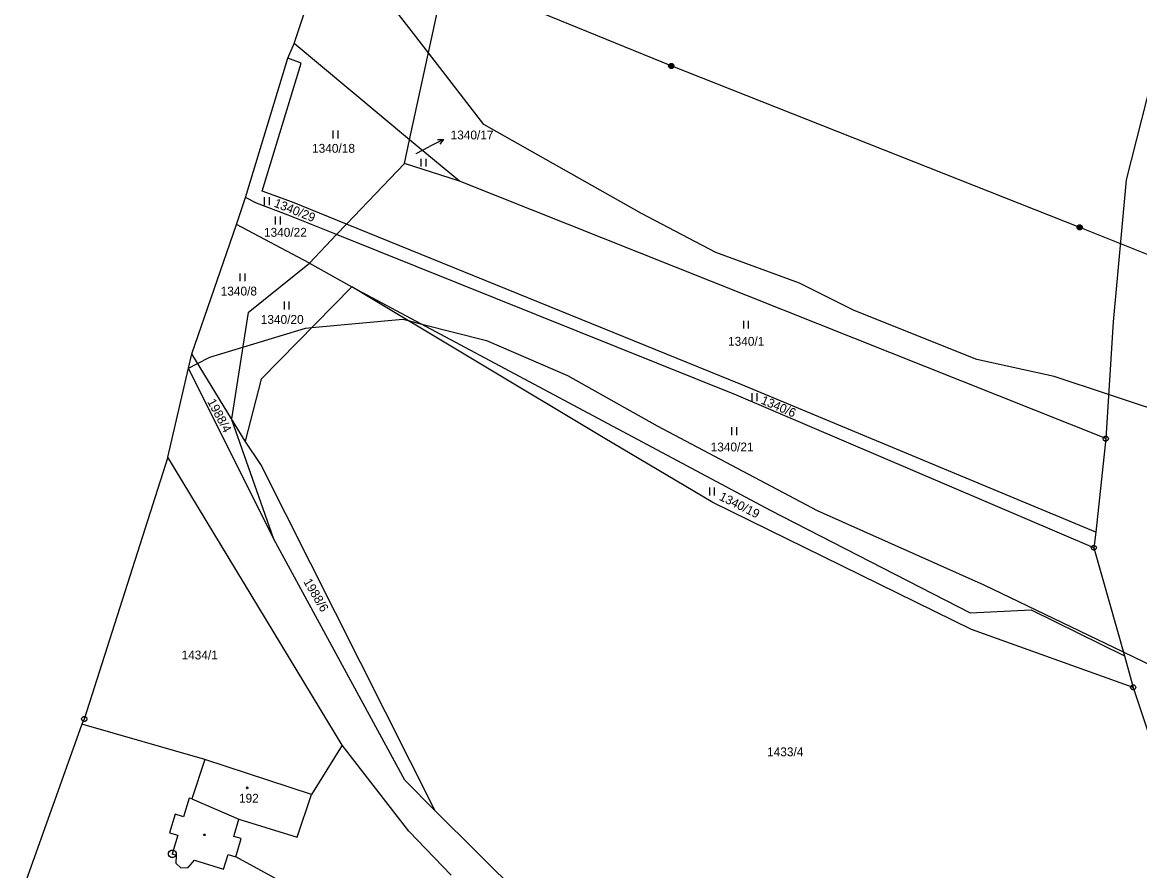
# Model space of a CAD drawing. Extents: x -789470 to -786707, y -1118640 to -1114455.
# Drawn here: x -787522.2 to -787308.1, y -1117682.3 to -1117519.8 of the extents above; entities that cross this region are included whole.
import ezdxf

# ---------------------------------------------------------------- set-up
doc = ezdxf.new("R2010")
doc.units = 0
for name, color, linetype in [('1', 7, 'Continuous'), ('11', 7, 'Continuous'), ('12', 7, 'Continuous'), ('2', 7, 'Continuous'), ('3', 7, 'Continuous'), ('4', 7, 'Continuous'), ('5', 7, 'Continuous'), ('6', 7, 'Continuous'), ('7', 7, 'Continuous'), ('8', 7, 'Continuous')]:
    doc.layers.add(name, color=color, linetype=linetype)

msp = doc.modelspace()

# ---------------------------------------------------------------- linework, layer by layer
at = {"layer": '1'}
for p, q in [((-787470.14, -1117523.83), (-787454.54, -1117476.95)), ((-787448.02, -1117542.27), (-787438.18, -1117497.19)), ((-787471.33, -1117526.59), (-787470.14, -1117523.83)), ((-787448.02, -1117542.27), (-787470.14, -1117523.83)), ((-787303.89, -1117523.03), (-787310.72, -1117549.93)), ((-787479.42, -1117553.33), (-787471.33, -1117526.59)), ((-787468.81, -1117527.55), (-787471.33, -1117526.59)), ((-787476.28, -1117552.12), (-787468.81, -1117527.55)), ((-787449, -1117546.78), (-787448.02, -1117542.27)), ((-787438.47, -1117550.22), (-787448.02, -1117542.27)), ((-787460.09, -1117558.43), (-787449, -1117546.78)), ((-787438.47, -1117550.22), (-787449, -1117546.78)), ((-787314.62, -1117599.54), (-787438.47, -1117550.22)), ((-787310.72, -1117549.93), (-787313.18, -1117577.14)), ((-787470.43, -1117554.23), (-787476.28, -1117552.12)), ((-787481.2, -1117558.5), (-787479.42, -1117553.33)), ((-787477.32, -1117554.4), (-787479.42, -1117553.33)), ((-787471.27, -1117556.71), (-787477.32, -1117554.4)), ((-787460.09, -1117558.43), (-787470.43, -1117554.23)), ((-787462, -1117560.43), (-787471.27, -1117556.71)), ((-787489.74, -1117583.27), (-787481.2, -1117558.5)), ((-787467.2, -1117565.89), (-787481.2, -1117558.5)), ((-787462, -1117560.43), (-787460.09, -1117558.43)), ((-787384.46, -1117589.14), (-787460.09, -1117558.43)), ((-787467.2, -1117565.89), (-787462, -1117560.43)), ((-787385.34, -1117591.22), (-787462, -1117560.43)), ((-787478.95, -1117575.34), (-787467.2, -1117565.89)), ((-787467.2, -1117565.89), (-787459.04, -1117570.42)), ((-787459.04, -1117570.42), (-787476.45, -1117588.13)), ((-787459.04, -1117570.42), (-787378.91, -1117613.22)), ((-787410.93, -1117599.34), (-787459.04, -1117570.42)), ((-787478.95, -1117575.34), (-787482.1, -1117595.77)), ((-787313.18, -1117577.14), (-787314.62, -1117599.54)), ((-787490.38, -1117586.02), (-787489.74, -1117583.27)), ((-787482.1, -1117595.77), (-787489.74, -1117583.27)), ((-787494.34, -1117603.08), (-787490.38, -1117586.02)), ((-787474.03, -1117618.82), (-787490.38, -1117586.02)), ((-787476.45, -1117588.13), (-787479.51, -1117600.01)), ((-787316.9, -1117620.47), (-787385.34, -1117591.22)), ((-787316.54, -1117617.47), (-787384.46, -1117589.14)), ((-787474.03, -1117618.82), (-787482.1, -1117595.77)), ((-787479.51, -1117600.01), (-787482.1, -1117595.77)), ((-787389.9, -1117611.79), (-787410.93, -1117599.34)), ((-787314.62, -1117599.54), (-787316.54, -1117617.47)), ((-787476.53, -1117604.49), (-787479.51, -1117600.01)), ((-787494.34, -1117603.08), (-787510.33, -1117653.28)), ((-787460.9, -1117658.31), (-787494.34, -1117603.08)), ((-787443.11, -1117670.88), (-787476.53, -1117604.49)), ((-787340.35, -1117636.15), (-787389.9, -1117611.79)), ((-787378.91, -1117613.22), (-787340.58, -1117632.95)), ((-787448.94, -1117665.02), (-787474.03, -1117618.82)), ((-787316.54, -1117617.47), (-787316.9, -1117620.47)), ((-787316.9, -1117620.47), (-787311.06, -1117641.19)), ((-787340.58, -1117632.95), (-787328.89, -1117632.33)), ((-787328.89, -1117632.33), (-787311.06, -1117641.19)), ((-787309.36, -1117647.22), (-787340.35, -1117636.15)), ((-787311.06, -1117641.19), (-787309.36, -1117647.22)), ((-787309.36, -1117647.22), (-787300.47, -1117674.13)), ((-787510.33, -1117653.28), (-787510.81, -1117654.24)), ((-787510.81, -1117654.24), (-787522.2, -1117686.13)), ((-787487.21, -1117661.01), (-787510.81, -1117654.24)), ((-787460.9, -1117658.31), (-787466.81, -1117667.72)), ((-787448.15, -1117674.77), (-787460.9, -1117658.31)), ((-787487.21, -1117661.01), (-787489.7, -1117668.58)), ((-787466.81, -1117667.72), (-787487.21, -1117661.01)), ((-787443.11, -1117670.88), (-787448.94, -1117665.02)), ((-787469.52, -1117675.95), (-787466.81, -1117667.72)), ((-787490.22, -1117668.42), (-787491.32, -1117672.03)), ((-787489.7, -1117668.58), (-787490.22, -1117668.42)), ((-787492.94, -1117671.54), (-787494.01, -1117675.06)), ((-787491.32, -1117672.03), (-787492.94, -1117671.54)), ((-787481.71, -1117675.77), (-787480.7, -1117672.45)), ((-787480.7, -1117672.45), (-787469.52, -1117675.95)), ((-787425.55, -1117688.26), (-787443.11, -1117670.88)), ((-787494.01, -1117675.06), (-787492.4, -1117675.55)), ((-787492.4, -1117675.55), (-787493.48, -1117679.11)), ((-787480.29, -1117676.2), (-787481.71, -1117675.77)), ((-787481.31, -1117679.68), (-787480.29, -1117676.2)), ((-787440.01, -1117683.2), (-787448.15, -1117674.77)), ((-787493.48, -1117679.11), (-787492.7, -1117679.35)), ((-787492.7, -1117679.35), (-787492.79, -1117680.93)), ((-787492.79, -1117680.93), (-787491.86, -1117681.81)), ((-787490.42, -1117681.76), (-787489.24, -1117680.32)), ((-787489.24, -1117680.32), (-787483.64, -1117682.04)), ((-787483.64, -1117682.04), (-787482.78, -1117679.22)), ((-787482.78, -1117679.22), (-787481.31, -1117679.68)), ((-787491.86, -1117681.81), (-787490.42, -1117681.76))]:
    msp.add_line(p, q, dxfattribs=at)
at = {"layer": '11'}
for points in [[(-787300.02, -1117595.72), (-787314.08, -1117591.07), (-787324.53, -1117587.62), (-787339.3, -1117584.36), (-787362.84, -1117575), (-787373.33, -1117569.71), (-787389.32, -1117563.89), (-787403.58, -1117556.41), (-787433.76, -1117539.31), (-787444.38, -1117525.57), (-787452.36, -1117515.25)], [(-787490.38, -1117586.03), (-787490.38, -1117586.03), (-787488.61, -1117585.12), (-787486.29, -1117583.92), (-787479.98, -1117582), (-787467.96, -1117578.37), (-787466.74, -1117578.25), (-787449.29, -1117576.63), (-787448.27, -1117576.89), (-787445.66, -1117577.57), (-787433.27, -1117580.76), (-787417.72, -1117587.42)], [(-787417.72, -1117587.42), (-787400.54, -1117597.07), (-787369.92, -1117613.34), (-787338, -1117627.53), (-787311.28, -1117640.41), (-787297.7, -1117646.95)]]:
    msp.add_lwpolyline(points, dxfattribs=at)
at = {"layer": '12'}
for p, q in [((-787487.21, -1117661.01), (-787489.7, -1117668.58)), ((-787466.81, -1117667.72), (-787487.21, -1117661.01)), ((-787469.52, -1117675.95), (-787466.81, -1117667.72)), ((-787489.7, -1117668.58), (-787480.7, -1117672.45)), ((-787480.7, -1117672.45), (-787469.52, -1117675.95))]:
    msp.add_line(p, q, dxfattribs=at)
at = {"layer": '3'}
for p, q in [((-787462.7, -1117540.49), (-787462.7, -1117541.99)), ((-787461.7, -1117541.99), (-787461.7, -1117540.49)), ((-787445.85, -1117545.9), (-787445.85, -1117547.4)), ((-787444.85, -1117547.4), (-787444.85, -1117545.9)), ((-787475.86, -1117553.28), (-787475.86, -1117554.78)), ((-787474.86, -1117554.78), (-787474.86, -1117553.28)), ((-787473.75, -1117556.99), (-787473.75, -1117558.49)), ((-787472.75, -1117558.49), (-787472.75, -1117556.99)), ((-787480.51, -1117567.89), (-787480.51, -1117569.39)), ((-787479.51, -1117569.39), (-787479.51, -1117567.89)), ((-787472.05, -1117573.26), (-787472.05, -1117574.76)), ((-787471.05, -1117574.76), (-787471.05, -1117573.26)), ((-787384.06, -1117576.95), (-787384.06, -1117578.45)), ((-787383.06, -1117578.45), (-787383.06, -1117576.95)), ((-787382.43, -1117590.84), (-787382.43, -1117592.34)), ((-787381.43, -1117592.34), (-787381.43, -1117590.84)), ((-787386.33, -1117597.35), (-787386.33, -1117598.85)), ((-787385.33, -1117598.85), (-787385.33, -1117597.35)), ((-787390.56, -1117608.92), (-787390.56, -1117610.42)), ((-787389.56, -1117610.42), (-787389.56, -1117608.92))]:
    msp.add_line(p, q, dxfattribs=at)
at = {"layer": '4'}
msp.add_line((-787489.7, -1117668.58), (-787480.7, -1117672.45), dxfattribs=at)
at = {"layer": '5'}
for points in [[(-787479.12, -1117666.3), (-787479.02, -1117666.32), (-787478.97, -1117666.41), (-787478.95, -1117666.47), (-787478.97, -1117666.56), (-787479.05, -1117666.63), (-787479.12, -1117666.64), (-787479.21, -1117666.61), (-787479.27, -1117666.55), (-787479.29, -1117666.47), (-787479.27, -1117666.38), (-787479.19, -1117666.31)], [(-787487.23, -1117675.32), (-787487.14, -1117675.47), (-787487.23, -1117675.62), (-787487.41, -1117675.62), (-787487.5, -1117675.47), (-787487.41, -1117675.32)]]:
    msp.add_lwpolyline(points, close=True, dxfattribs=at)
at = {"layer": '6'}
for p, q in [((-787397.87, -1117528.11), (-787459.81, -1117502.65)), ((-787319.62, -1117559.06), (-787397.87, -1117528.11)), ((-787284.66, -1117573.13), (-787319.62, -1117559.06)), ((-787400.35, -1117723.7), (-787481.31, -1117679.68))]:
    msp.add_line(p, q, dxfattribs=at)
for points in [[(-787398.02, -1117527.63), (-787397.71, -1117527.63), (-787397.46, -1117527.81), (-787397.36, -1117528.1), (-787397.46, -1117528.39), (-787397.71, -1117528.57), (-787398.02, -1117528.57), (-787398.27, -1117528.39), (-787398.37, -1117528.1), (-787398.27, -1117527.81), (-787398.02, -1117527.63), (-787397.99, -1117527.67), (-787397.75, -1117527.67), (-787397.59, -1117527.75), (-787398.15, -1117527.75), (-787398.23, -1117527.83), (-787397.51, -1117527.83), (-787397.51, -1117527.91), (-787398.23, -1117527.91), (-787398.27, -1117527.99), (-787397.47, -1117527.99), (-787397.43, -1117528.07), (-787398.31, -1117528.07), (-787398.31, -1117528.15), (-787397.43, -1117528.15), (-787397.46, -1117528.23), (-787398.27, -1117528.23), (-787398.26, -1117528.31), (-787397.45, -1117528.31), (-787397.5, -1117528.39), (-787398.22, -1117528.39), (-787398.14, -1117528.47), (-787397.58, -1117528.47), (-787397.69, -1117528.55), (-787398.03, -1117528.55)], [(-787319.77, -1117558.58), (-787319.46, -1117558.58), (-787319.21, -1117558.76), (-787319.11, -1117559.05), (-787319.21, -1117559.34), (-787319.46, -1117559.52), (-787319.77, -1117559.52), (-787320.02, -1117559.34), (-787320.12, -1117559.05), (-787320.02, -1117558.76), (-787319.77, -1117558.58), (-787319.74, -1117558.62), (-787319.5, -1117558.62), (-787319.34, -1117558.7), (-787319.9, -1117558.7), (-787319.98, -1117558.78), (-787319.26, -1117558.78), (-787319.26, -1117558.86), (-787319.98, -1117558.86), (-787320.02, -1117558.94), (-787319.22, -1117558.94), (-787319.18, -1117559.02), (-787320.06, -1117559.02), (-787320.06, -1117559.1), (-787319.18, -1117559.1), (-787319.21, -1117559.18), (-787320.02, -1117559.18), (-787320.01, -1117559.26), (-787319.2, -1117559.26), (-787319.25, -1117559.34), (-787319.97, -1117559.34), (-787319.89, -1117559.42), (-787319.33, -1117559.42), (-787319.44, -1117559.5), (-787319.78, -1117559.5)]]:
    msp.add_lwpolyline(points, dxfattribs=at)
at = {"layer": '7'}
for p in [(-787446.75, -1117544.92), (-787441.54, -1117542.19)]:
    msp.add_line(p, (-787444.2, -1117543.58), dxfattribs=at)
msp.add_lwpolyline([(-787442.66, -1117542.21), (-787441.54, -1117542.19), (-787442.2, -1117543.09)], dxfattribs=at)
at = {"layer": '8'}
for p, q in [((-787314.74, -1117599.54), (-787314.5, -1117599.54)), ((-787317.02, -1117620.47), (-787316.78, -1117620.47)), ((-787309.48, -1117647.22), (-787309.24, -1117647.22)), ((-787510.45, -1117653.28), (-787510.21, -1117653.28)), ((-787493.53, -1117679.11), (-787493.43, -1117679.11))]:
    msp.add_line(p, q, dxfattribs=at)
for points in [[(-787314.47, -1117599.06), (-787314.22, -1117599.24), (-787314.12, -1117599.53), (-787314.22, -1117599.82), (-787314.47, -1117600), (-787314.78, -1117600), (-787315.03, -1117599.82), (-787315.13, -1117599.53), (-787315.03, -1117599.24), (-787314.78, -1117599.06)], [(-787316.75, -1117619.99), (-787316.5, -1117620.17), (-787316.4, -1117620.46), (-787316.5, -1117620.75), (-787316.75, -1117620.93), (-787317.06, -1117620.93), (-787317.31, -1117620.75), (-787317.41, -1117620.46), (-787317.31, -1117620.17), (-787317.06, -1117619.99)], [(-787309.21, -1117646.74), (-787308.96, -1117646.92), (-787308.86, -1117647.21), (-787308.96, -1117647.5), (-787309.21, -1117647.68), (-787309.52, -1117647.68), (-787309.77, -1117647.5), (-787309.87, -1117647.21), (-787309.77, -1117646.92), (-787309.52, -1117646.74)], [(-787510.18, -1117652.8), (-787509.93, -1117652.98), (-787509.83, -1117653.27), (-787509.93, -1117653.56), (-787510.18, -1117653.74), (-787510.49, -1117653.74), (-787510.74, -1117653.56), (-787510.84, -1117653.27), (-787510.74, -1117652.98), (-787510.49, -1117652.8)], [(-787493.29, -1117678.39), (-787492.95, -1117678.58), (-787492.76, -1117678.92), (-787492.76, -1117679.31), (-787492.95, -1117679.65), (-787493.29, -1117679.84), (-787493.68, -1117679.84), (-787494.02, -1117679.65), (-787494.21, -1117679.31), (-787494.21, -1117678.92), (-787494.02, -1117678.58), (-787493.68, -1117678.39)]]:
    msp.add_lwpolyline(points, close=True, dxfattribs=at)

# ---------------------------------------------------------------- texts
at = {"layer": '2'}
for s, height, p in [('1340/18', 1.7, (-787466.69, -1117544.75)), ('1340/17', 0.1, (-787447, -1117544.92)), ('1340/22', 1.7, (-787475.91, -1117560.85)), ('1340/8', 1.7, (-787484.2, -1117572.11)), ('1340/20', 1.7, (-787476.52, -1117577.54)), ('1340/1', 1.7, (-787386.99, -1117581.74)), ('1340/21', 1.7, (-787390.32, -1117601.99)), ('1434/1', 1.7, (-787491.7, -1117641.86)), ('1433/4', 1.7, (-787379.51, -1117660.42)), ('192', 1.7, (-787480.7, -1117669.31))]:
    msp.add_text(s, height=height, dxfattribs=at).set_placement(p)
for s, rotation, p in [('1340/29', 338.2743, (-787474.13, -1117555.03)), ('1988/4', 298.2245, (-787486.82, -1117592.44)), ('1340/6', 336.8419, (-787380.83, -1117592.78)), ('1340/19', 333.4614, (-787388.83, -1117611.2)), ('1988/6', 300.5164, (-787468.41, -1117626.95))]:
    msp.add_text(s, height=1.7, rotation=rotation, dxfattribs=at).set_placement(p)
at = {"layer": '7'}
msp.add_text('1340/17', height=1.7, dxfattribs=at).set_placement((-787440.15, -1117542.19))

doc.saveas('drawing.dxf')
